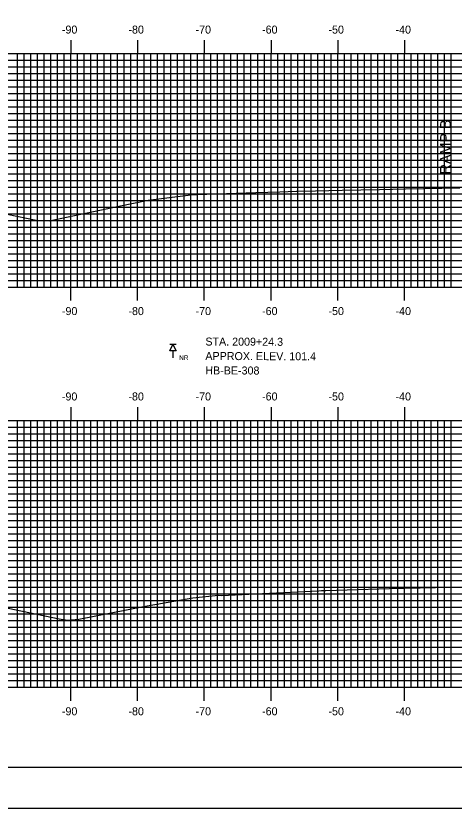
# Model space of a CAD drawing. Extents: x 853107 to 853450, y 366605 to 366825.
# Drawn here: x 853174.3 to 853239.9, y 366604.9 to 366723.7 of the extents above; entities that cross this region are included whole.
import ezdxf

# ---------------------------------------------------------------- set-up
doc = ezdxf.new("R2010")
doc.units = 0
for name, color, linetype in [('ANNOTATION', 7, 'Continuous'), ('BORDER', 7, 'Continuous'), ('BORING - NO REFUSAL', 7, 'Continuous'), ('H_V ANNOTATION', 7, 'Continuous'), ('M_Roadway_Centerline', 7, 'Continuous'), ('MAJOR', 7, 'Continuous'), ('MINOR', 7, 'Continuous'), ('PLOT BOUNDARY', 7, 'Continuous'), ('S_Roadway_Centerline', 7, 'Continuous')]:
    doc.layers.add(name, color=color, linetype=linetype)

msp = doc.modelspace()

# ---------------------------------------------------------------- linework, layer by layer
at = {"layer": 'BORDER'}
msp.add_lwpolyline([(853122.9, 366611.06), (853442.9, 366611.06), (853442.9, 366821.06), (853122.9, 366821.06)], close=True, dxfattribs=at)
at = {"layer": 'BORING - NO REFUSAL'}
for p, q in [((853198.28, 366674.46), (853197.32, 366674.46)), ((853197.8, 366673.5), (853197.8, 366672.44))]:
    msp.add_line(p, q, dxfattribs=at)
msp.add_lwpolyline([(853197.8, 366674.46), (853198.28, 366673.5), (853197.32, 366673.5)], close=True, dxfattribs=at)
at = {"layer": 'MAJOR'}
for p, q in [((853182.5, 366720.06), (853182.5, 366718.06)), ((853192.5, 366720.06), (853192.5, 366718.06)), ((853202.5, 366720.06), (853202.5, 366718.06)), ((853212.5, 366720.06), (853212.5, 366718.06)), ((853222.5, 366720.06), (853222.5, 366718.06)), ((853232.5, 366720.06), (853232.5, 366718.06)), ((853132.5, 366718.06), (853412.5, 366718.06)), ((853132.5, 366718.06), (853412.5, 366718.06)), ((853182.5, 366683.06), (853182.5, 366718.06)), ((853192.5, 366683.06), (853192.5, 366718.06)), ((853202.5, 366683.06), (853202.5, 366718.06)), ((853212.5, 366683.06), (853212.5, 366718.06)), ((853222.5, 366683.06), (853222.5, 366718.06)), ((853232.5, 366683.06), (853232.5, 366718.06)), ((853132.5, 366713.06), (853412.5, 366713.06)), ((853132.5, 366708.06), (853412.5, 366708.06)), ((853132.5, 366703.06), (853412.5, 366703.06)), ((853132.5, 366698.06), (853412.5, 366698.06)), ((853132.5, 366693.06), (853412.5, 366693.06)), ((853132.5, 366688.06), (853412.5, 366688.06)), ((853132.5, 366683.06), (853412.5, 366683.06)), ((853132.5, 366683.06), (853412.5, 366683.06)), ((853182.5, 366681.05), (853182.5, 366683.06)), ((853192.5, 366681.05), (853192.5, 366683.06)), ((853202.5, 366681.05), (853202.5, 366683.06)), ((853212.5, 366681.05), (853212.5, 366683.06)), ((853222.5, 366681.05), (853222.5, 366683.06)), ((853232.5, 366681.05), (853232.5, 366683.06)), ((853182.5, 366665.06), (853182.5, 366663.06)), ((853192.5, 366665.06), (853192.5, 366663.06)), ((853202.5, 366665.06), (853202.5, 366663.06)), ((853212.5, 366665.06), (853212.5, 366663.06)), ((853222.5, 366665.06), (853222.5, 366663.06)), ((853232.5, 366665.06), (853232.5, 366663.06)), ((853132.5, 366663.06), (853412.5, 366663.06)), ((853132.5, 366663.06), (853412.5, 366663.06)), ((853182.5, 366623.06), (853182.5, 366663.06)), ((853192.5, 366623.06), (853192.5, 366663.06)), ((853202.5, 366623.06), (853202.5, 366663.06)), ((853212.5, 366623.06), (853212.5, 366663.06)), ((853222.5, 366623.06), (853222.5, 366663.06)), ((853232.5, 366623.06), (853232.5, 366663.06)), ((853132.5, 366658.06), (853412.5, 366658.06)), ((853132.5, 366653.06), (853412.5, 366653.06)), ((853132.5, 366648.06), (853412.5, 366648.06)), ((853132.5, 366643.06), (853412.5, 366643.06)), ((853132.5, 366638.06), (853412.5, 366638.06)), ((853132.5, 366633.06), (853412.5, 366633.06)), ((853132.5, 366628.06), (853412.5, 366628.06)), ((853132.5, 366623.06), (853412.5, 366623.06)), ((853132.5, 366623.06), (853412.5, 366623.06)), ((853182.5, 366621.05), (853182.5, 366623.06)), ((853192.5, 366621.05), (853192.5, 366623.06)), ((853202.5, 366621.05), (853202.5, 366623.06)), ((853212.5, 366621.05), (853212.5, 366623.06)), ((853222.5, 366621.05), (853222.5, 366623.06)), ((853232.5, 366621.05), (853232.5, 366623.06))]:
    msp.add_line(p, q, dxfattribs=at)
at = {"layer": 'MINOR'}
for p, q in [((853174.5, 366683.06), (853174.5, 366718.06)), ((853175.5, 366683.06), (853175.5, 366718.06)), ((853176.5, 366683.06), (853176.5, 366718.06)), ((853177.5, 366683.06), (853177.5, 366718.06)), ((853178.5, 366683.06), (853178.5, 366718.06)), ((853179.5, 366683.06), (853179.5, 366718.06)), ((853180.5, 366683.06), (853180.5, 366718.06)), ((853181.5, 366683.06), (853181.5, 366718.06)), ((853183.5, 366683.06), (853183.5, 366718.06)), ((853184.5, 366683.06), (853184.5, 366718.06)), ((853185.5, 366683.06), (853185.5, 366718.06)), ((853186.5, 366683.06), (853186.5, 366718.06)), ((853187.5, 366683.06), (853187.5, 366718.06)), ((853188.5, 366683.06), (853188.5, 366718.06)), ((853189.5, 366683.06), (853189.5, 366718.06)), ((853190.5, 366683.06), (853190.5, 366718.06)), ((853191.5, 366683.06), (853191.5, 366718.06)), ((853193.5, 366683.06), (853193.5, 366718.06)), ((853194.5, 366683.06), (853194.5, 366718.06)), ((853195.5, 366683.06), (853195.5, 366718.06)), ((853196.5, 366683.06), (853196.5, 366718.06)), ((853197.5, 366683.06), (853197.5, 366718.06)), ((853198.5, 366683.06), (853198.5, 366718.06)), ((853199.5, 366683.06), (853199.5, 366718.06)), ((853200.5, 366683.06), (853200.5, 366718.06)), ((853201.5, 366683.06), (853201.5, 366718.06)), ((853203.5, 366683.06), (853203.5, 366718.06)), ((853204.5, 366683.06), (853204.5, 366718.06)), ((853205.5, 366683.06), (853205.5, 366718.06)), ((853206.5, 366683.06), (853206.5, 366718.06)), ((853207.5, 366683.06), (853207.5, 366718.06)), ((853208.5, 366683.06), (853208.5, 366718.06)), ((853209.5, 366683.06), (853209.5, 366718.06)), ((853210.5, 366683.06), (853210.5, 366718.06)), ((853211.5, 366683.06), (853211.5, 366718.06)), ((853213.5, 366683.06), (853213.5, 366718.06)), ((853214.5, 366683.06), (853214.5, 366718.06)), ((853215.5, 366683.06), (853215.5, 366718.06)), ((853216.5, 366683.06), (853216.5, 366718.06)), ((853217.5, 366683.06), (853217.5, 366718.06)), ((853218.5, 366683.06), (853218.5, 366718.06)), ((853219.5, 366683.06), (853219.5, 366718.06)), ((853220.5, 366683.06), (853220.5, 366718.06)), ((853221.5, 366683.06), (853221.5, 366718.06)), ((853223.5, 366683.06), (853223.5, 366718.06)), ((853224.5, 366683.06), (853224.5, 366718.06)), ((853225.5, 366683.06), (853225.5, 366718.06)), ((853226.5, 366683.06), (853226.5, 366718.06)), ((853227.5, 366683.06), (853227.5, 366718.06)), ((853228.5, 366683.06), (853228.5, 366718.06)), ((853229.5, 366683.06), (853229.5, 366718.06)), ((853230.5, 366683.06), (853230.5, 366718.06)), ((853231.5, 366683.06), (853231.5, 366718.06)), ((853233.5, 366683.06), (853233.5, 366718.06)), ((853234.5, 366683.06), (853234.5, 366718.06)), ((853235.5, 366683.06), (853235.5, 366718.06)), ((853236.5, 366683.06), (853236.5, 366718.06)), ((853237.5, 366683.06), (853237.5, 366718.06)), ((853238.5, 366683.06), (853238.5, 366718.06)), ((853239.5, 366683.06), (853239.5, 366718.06)), ((853132.5, 366717.06), (853412.5, 366717.06)), ((853132.5, 366716.06), (853412.5, 366716.06)), ((853132.5, 366715.06), (853412.5, 366715.06)), ((853132.5, 366714.06), (853412.5, 366714.06)), ((853132.5, 366712.06), (853412.5, 366712.06)), ((853132.5, 366711.06), (853412.5, 366711.06)), ((853132.5, 366710.06), (853412.5, 366710.06)), ((853132.5, 366709.06), (853412.5, 366709.06)), ((853132.5, 366707.06), (853412.5, 366707.06)), ((853132.5, 366706.06), (853412.5, 366706.06)), ((853132.5, 366705.06), (853412.5, 366705.06)), ((853132.5, 366704.06), (853412.5, 366704.06)), ((853132.5, 366702.06), (853412.5, 366702.06)), ((853132.5, 366701.06), (853412.5, 366701.06)), ((853132.5, 366700.06), (853412.5, 366700.06)), ((853132.5, 366699.06), (853412.5, 366699.06)), ((853132.5, 366697.06), (853412.5, 366697.06)), ((853132.5, 366696.06), (853412.5, 366696.06)), ((853132.5, 366695.06), (853412.5, 366695.06)), ((853132.5, 366694.06), (853412.5, 366694.06)), ((853132.5, 366692.06), (853412.5, 366692.06)), ((853132.5, 366691.06), (853412.5, 366691.06)), ((853132.5, 366690.06), (853412.5, 366690.06)), ((853132.5, 366689.06), (853412.5, 366689.06)), ((853132.5, 366687.06), (853412.5, 366687.06)), ((853132.5, 366686.06), (853412.5, 366686.06)), ((853132.5, 366685.06), (853412.5, 366685.06)), ((853132.5, 366684.06), (853412.5, 366684.06)), ((853174.5, 366623.06), (853174.5, 366663.06)), ((853175.5, 366623.06), (853175.5, 366663.06)), ((853176.5, 366623.06), (853176.5, 366663.06)), ((853177.5, 366623.06), (853177.5, 366663.06)), ((853178.5, 366623.06), (853178.5, 366663.06)), ((853179.5, 366623.06), (853179.5, 366663.06)), ((853180.5, 366623.06), (853180.5, 366663.06)), ((853181.5, 366623.06), (853181.5, 366663.06)), ((853183.5, 366623.06), (853183.5, 366663.06)), ((853184.5, 366623.06), (853184.5, 366663.06)), ((853185.5, 366623.06), (853185.5, 366663.06)), ((853186.5, 366623.06), (853186.5, 366663.06)), ((853187.5, 366623.06), (853187.5, 366663.06)), ((853188.5, 366623.06), (853188.5, 366663.06)), ((853189.5, 366623.06), (853189.5, 366663.06)), ((853190.5, 366623.06), (853190.5, 366663.06)), ((853191.5, 366623.06), (853191.5, 366663.06)), ((853193.5, 366623.06), (853193.5, 366663.06)), ((853194.5, 366623.06), (853194.5, 366663.06)), ((853195.5, 366623.06), (853195.5, 366663.06)), ((853196.5, 366623.06), (853196.5, 366663.06)), ((853197.5, 366623.06), (853197.5, 366663.06)), ((853198.5, 366623.06), (853198.5, 366663.06)), ((853199.5, 366623.06), (853199.5, 366663.06)), ((853200.5, 366623.06), (853200.5, 366663.06)), ((853201.5, 366623.06), (853201.5, 366663.06)), ((853203.5, 366623.06), (853203.5, 366663.06)), ((853204.5, 366623.06), (853204.5, 366663.06)), ((853205.5, 366623.06), (853205.5, 366663.06)), ((853206.5, 366623.06), (853206.5, 366663.06)), ((853207.5, 366623.06), (853207.5, 366663.06)), ((853208.5, 366623.06), (853208.5, 366663.06)), ((853209.5, 366623.06), (853209.5, 366663.06)), ((853210.5, 366623.06), (853210.5, 366663.06)), ((853211.5, 366623.06), (853211.5, 366663.06)), ((853213.5, 366623.06), (853213.5, 366663.06)), ((853214.5, 366623.06), (853214.5, 366663.06)), ((853215.5, 366623.06), (853215.5, 366663.06)), ((853216.5, 366623.06), (853216.5, 366663.06)), ((853217.5, 366623.06), (853217.5, 366663.06)), ((853218.5, 366623.06), (853218.5, 366663.06)), ((853219.5, 366623.06), (853219.5, 366663.06)), ((853220.5, 366623.06), (853220.5, 366663.06)), ((853221.5, 366623.06), (853221.5, 366663.06)), ((853223.5, 366623.06), (853223.5, 366663.06)), ((853224.5, 366623.06), (853224.5, 366663.06)), ((853225.5, 366623.06), (853225.5, 366663.06)), ((853226.5, 366623.06), (853226.5, 366663.06)), ((853227.5, 366623.06), (853227.5, 366663.06)), ((853228.5, 366623.06), (853228.5, 366663.06)), ((853229.5, 366623.06), (853229.5, 366663.06)), ((853230.5, 366623.06), (853230.5, 366663.06)), ((853231.5, 366623.06), (853231.5, 366663.06)), ((853233.5, 366623.06), (853233.5, 366663.06)), ((853234.5, 366623.06), (853234.5, 366663.06)), ((853235.5, 366623.06), (853235.5, 366663.06)), ((853236.5, 366623.06), (853236.5, 366663.06)), ((853237.5, 366623.06), (853237.5, 366663.06)), ((853238.5, 366623.06), (853238.5, 366663.06)), ((853239.5, 366623.06), (853239.5, 366663.06)), ((853132.5, 366662.06), (853412.5, 366662.06)), ((853132.5, 366661.06), (853412.5, 366661.06)), ((853132.5, 366660.06), (853412.5, 366660.06)), ((853132.5, 366659.06), (853412.5, 366659.06)), ((853132.5, 366657.06), (853412.5, 366657.06)), ((853132.5, 366656.06), (853412.5, 366656.06)), ((853132.5, 366655.06), (853412.5, 366655.06)), ((853132.5, 366654.06), (853412.5, 366654.06)), ((853132.5, 366652.06), (853412.5, 366652.06)), ((853132.5, 366651.06), (853412.5, 366651.06)), ((853132.5, 366650.06), (853412.5, 366650.06)), ((853132.5, 366649.06), (853412.5, 366649.06)), ((853132.5, 366647.06), (853412.5, 366647.06)), ((853132.5, 366646.06), (853412.5, 366646.06)), ((853132.5, 366645.06), (853412.5, 366645.06)), ((853132.5, 366644.06), (853412.5, 366644.06)), ((853132.5, 366642.06), (853412.5, 366642.06)), ((853132.5, 366641.06), (853412.5, 366641.06)), ((853132.5, 366640.06), (853412.5, 366640.06)), ((853132.5, 366639.06), (853412.5, 366639.06)), ((853132.5, 366637.06), (853412.5, 366637.06)), ((853132.5, 366636.06), (853412.5, 366636.06)), ((853132.5, 366635.06), (853412.5, 366635.06)), ((853132.5, 366634.06), (853412.5, 366634.06)), ((853132.5, 366632.06), (853412.5, 366632.06)), ((853132.5, 366631.06), (853412.5, 366631.06)), ((853132.5, 366630.06), (853412.5, 366630.06)), ((853132.5, 366629.06), (853412.5, 366629.06)), ((853132.5, 366627.06), (853412.5, 366627.06)), ((853132.5, 366626.06), (853412.5, 366626.06)), ((853132.5, 366625.06), (853412.5, 366625.06)), ((853132.5, 366624.06), (853412.5, 366624.06))]:
    msp.add_line(p, q, dxfattribs=at)
at = {"layer": 'PLOT BOUNDARY'}
msp.add_lwpolyline([(853106.72, 366604.94), (853446.72, 366604.94), (853446.72, 366824.94), (853106.72, 366824.94)], close=True, dxfattribs=at)
at = {"layer": 'S_Roadway_Centerline'}
for points in [[(853132.5, 366711.19), (853136.15, 366709.79), (853139.47, 366708.14), (853166.29, 366696.15), (853172.98, 366694.01), (853177.28, 366693.08), (853179.23, 366692.99), (853189.7, 366695.2), (853194.1, 366696.11), (853200.88, 366696.93), (853201.43, 366696.92), (853210.25, 366697.23), (853213.84, 366697.36), (853216.32, 366697.44), (853216.51, 366697.43), (853219.19, 366697.5), (853223.14, 366697.57), (853228.77, 366697.71), (853232.64, 366697.78), (853240.8, 366697.96)], [(853132.5, 366653.68), (853135.46, 366652.34), (853147.22, 366646.73), (853147.98, 366646.36), (853148.84, 366645.94), (853166.58, 366637.15), (853173.1, 366634.9), (853180.75, 366633.34), (853182.02, 366633.1), (853183.71, 366633.28), (853193.39, 366635.16), (853200.79, 366636.45), (853204.64, 366636.88), (853205.13, 366636.82), (853210.17, 366637.08), (853219.65, 366637.54), (853220.08, 366637.56), (853220.74, 366637.58), (853223.92, 366637.67), (853230.24, 366637.86), (853241.74, 366638.1)]]:
    msp.add_lwpolyline(points, dxfattribs=at)

# ---------------------------------------------------------------- texts
at = {"layer": 'ANNOTATION'}
msp.add_text('RAMP B', height=1.6, rotation=90, dxfattribs=at).set_placement((853239.44, 366699.96))
at = {"layer": 'BORING - NO REFUSAL'}
for s, p in [('STA. 2009+24.3', (853202.66, 366674.29)), ('APPROX. ELEV. 101.4', (853202.66, 366672.13)), ('HB-BE-308', (853202.65, 366669.97))]:
    msp.add_text(s, height=1.2, rotation=359.8142, dxfattribs=at).set_placement(p)
msp.add_text('NR', height=0.7, dxfattribs=at).set_placement((853198.74, 366672.12))
at = {"layer": 'H_V ANNOTATION'}
for s, p in [('-90', (853181.16, 366721.06)), ('-80', (853191.13, 366721.06)), ('-70', (853201.19, 366721.06)), ('-60', (853211.16, 366721.06)), ('-50', (853221.11, 366721.06)), ('-40', (853231.16, 366721.06)), ('-90', (853181.16, 366678.86)), ('-80', (853191.13, 366678.86)), ('-70', (853201.19, 366678.86)), ('-60', (853211.16, 366678.86)), ('-50', (853221.11, 366678.86)), ('-40', (853231.16, 366678.86)), ('-90', (853181.16, 366666.06)), ('-80', (853191.13, 366666.06)), ('-70', (853201.19, 366666.06)), ('-60', (853211.16, 366666.06)), ('-50', (853221.11, 366666.06)), ('-40', (853231.16, 366666.06)), ('-90', (853181.16, 366618.86)), ('-80', (853191.13, 366618.86)), ('-70', (853201.19, 366618.86)), ('-60', (853211.16, 366618.86)), ('-50', (853221.11, 366618.86)), ('-40', (853231.16, 366618.86))]:
    msp.add_text(s, height=1.2, dxfattribs=at).set_placement(p)
at = {"layer": 'M_Roadway_Centerline'}
for s, p in [('C', (853216.51, 366697.43)), ('L', (853216.51, 366697.43)), ('C', (853220.08, 366637.56)), ('L', (853220.08, 366637.56))]:
    msp.add_text(s, height=0.0146, dxfattribs=at).set_placement(p)

doc.saveas('drawing.dxf')
